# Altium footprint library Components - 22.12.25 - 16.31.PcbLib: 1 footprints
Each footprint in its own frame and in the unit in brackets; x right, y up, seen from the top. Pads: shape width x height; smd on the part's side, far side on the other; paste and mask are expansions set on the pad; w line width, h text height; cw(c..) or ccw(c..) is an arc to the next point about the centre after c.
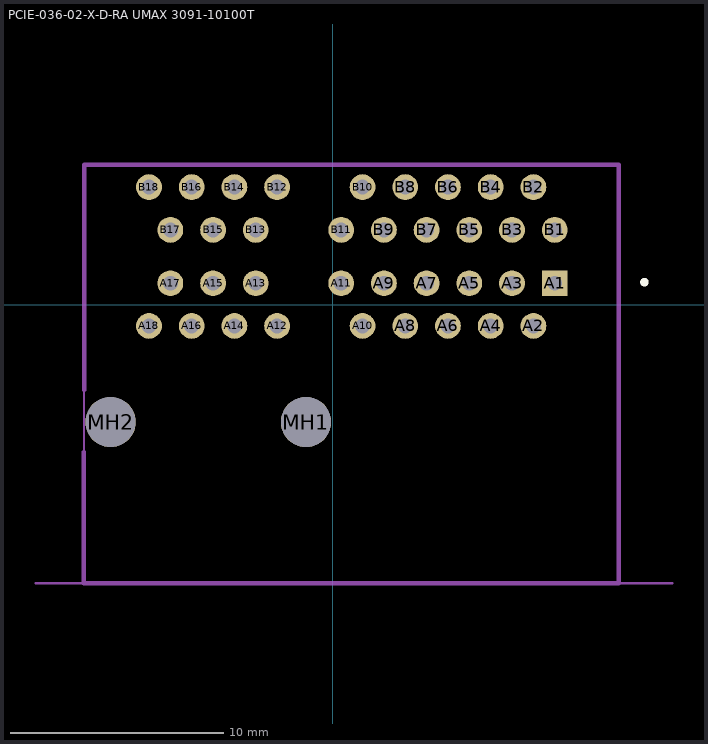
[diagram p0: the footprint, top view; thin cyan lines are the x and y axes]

## PCIE-036-02-X-D-RA UMAX 3091-10100T [mm]
pads (38):
  rect 1.208x1.208 / inner round 1.116 / far side rect 1.208x1.208 hole 0.7: A1(10.4,1)
  round 1.208 hole 0.7: A2(9.4,-1) A3(8.4,1) A4(7.4,-1) A5(6.4,1) A6(5.4,-1) A7(4.4,1) A8(3.4,-1) A9(2.4,1) A10(1.4,-1) A11(0.4,1) A12(-2.6,-1) A13(-3.6,1) A14(-4.6,-1) A15(-5.6,1) A16(-6.6,-1) A17(-7.6,1) A18(-8.6,-1) B1(10.4,3.5) B2(9.4,5.5) B3(8.4,3.5) B4(7.4,5.5) B5(6.4,3.5) B6(5.4,5.5) B7(4.4,3.5) B8(3.4,5.5) B9(2.4,3.5) B10(1.4,5.5) B11(0.4,3.5) B12(-2.6,5.5) B13(-3.6,3.5) B14(-4.6,5.5) B15(-5.6,3.5) B16(-6.6,5.5) B17(-7.6,3.5) B18(-8.6,5.5)
  round 2.35 hole 2.35 unplated: MH1(-1.25,-5.5) MH2(-10.4,-5.5)
Top Overlay:
  circle w0.2: c14.6,1.05 r0.1
Mechanical 3:
  lines w0.1: -13.9,-13.05 15.9,-13.05 ; -11.65,-13.05 -11.65,6.55 13.4,6.55 13.4,-13.05
  lines w0.127: -11.65,-13.05 13.4,-13.05
Mechanical 7:
  lines w0.2: -11.65,-6.9 -11.65,-13.05 13.4,-13.05 13.4,6.55 -11.636,6.55 -11.636,-4
3D body "PCIE-036-02-S-D-RA.stp": height 9.15, standoff -4.71, extent -11.591,-13.018 13.409,5.832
